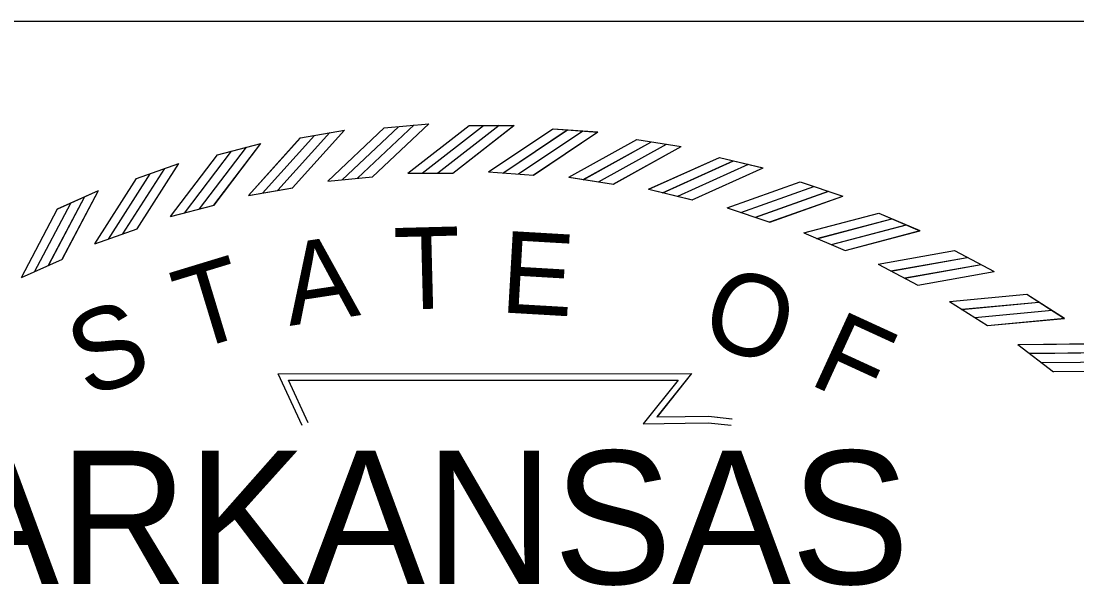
# Model space of a CAD drawing. Extents: x 0 to 1228740, y 0 to 152440.
# Drawn here: x 31.519 to 32.801, y 19.458 to 20.143 of the extents above; entities that cross this region are included whole.
import ezdxf

# ---------------------------------------------------------------- set-up
doc = ezdxf.new("R2010")
doc.units = 0
for name, color, linetype in [('R_Border', 7, 'Continuous'), ('STAMP_Byron', 7, 'Continuous'), ('STAMP_Landon', 7, 'Continuous'), ('STAMP_PP', 7, 'Continuous')]:
    doc.layers.add(name, color=color, linetype=linetype)

msp = doc.modelspace()

# ---------------------------------------------------------------- linework, layer by layer
at = {"layer": 'R_Border'}
msp.add_line((29.1131, 20.1432), (33.4231, 20.1432), dxfattribs=at)
at = {"layer": 'STAMP_Byron'}
for p, q in [((31.8584, 20.0015), (31.912, 20.011)), ((31.8584, 20.0015), (31.912, 20.011)), ((31.9603, 20.0137), (32.0145, 20.0187)), ((31.9603, 20.0137), (32.0145, 20.0187)), ((32.0633, 20.0167), (32.1177, 20.0167)), ((32.0633, 20.0167), (32.1177, 20.0167)), ((32.1652, 20.0126), (32.2195, 20.0087)), ((32.1652, 20.0126), (32.2195, 20.0087)), ((32.2669, 19.9994), (32.3207, 19.991)), ((32.2669, 19.9994), (32.3207, 19.991)), ((31.758, 19.981), (31.8106, 19.9948)), ((31.758, 19.981), (31.8106, 19.9948)), ((31.6595, 19.9522), (31.7108, 19.9704)), ((31.6595, 19.9522), (31.7108, 19.9704)), ((32.3672, 19.9779), (32.4201, 19.965)), ((32.3672, 19.9779), (32.4201, 19.965)), ((31.9891, 19.9588), (32.0436, 19.9588)), ((31.9891, 19.9588), (32.0436, 19.9588)), ((32.0869, 19.9604), (32.1413, 19.9564)), ((32.0869, 19.9604), (32.1413, 19.9564)), ((31.8917, 19.9492), (31.946, 19.9542)), ((31.8917, 19.9492), (31.946, 19.9542)), ((32.1846, 19.9538), (32.2385, 19.9453)), ((32.1846, 19.9538), (32.2385, 19.9453)), ((32.4653, 19.9481), (32.517, 19.9309)), ((32.4653, 19.9481), (32.517, 19.9309)), ((31.5638, 19.9154), (31.6134, 19.9377)), ((31.5638, 19.9154), (31.6134, 19.9377)), ((31.7954, 19.9316), (31.8491, 19.9411)), ((31.7954, 19.9316), (31.8491, 19.9411)), ((32.2814, 19.9392), (32.3344, 19.9263)), ((32.2814, 19.9392), (32.3344, 19.9263)), ((31.7009, 19.9061), (31.7536, 19.92)), ((31.7009, 19.9061), (31.7536, 19.92)), ((32.3766, 19.9166), (32.4283, 19.8994)), ((32.3766, 19.9166), (32.4283, 19.8994)), ((32.5607, 19.9103), (32.6107, 19.889)), ((32.5607, 19.9103), (32.6107, 19.889)), ((31.6088, 19.8729), (31.6602, 19.8911)), ((31.6088, 19.8729), (31.6602, 19.8911)), ((32.4697, 19.8863), (32.5198, 19.8649)), ((32.4697, 19.8863), (32.5198, 19.8649)), ((32.6526, 19.8648), (32.7007, 19.8394)), ((32.6526, 19.8648), (32.7007, 19.8394)), ((31.5198, 19.8322), (31.5696, 19.8545)), ((31.5198, 19.8322), (31.5696, 19.8545)), ((32.5599, 19.8484), (32.6081, 19.8229)), ((32.5599, 19.8484), (32.6081, 19.8229)), ((32.7404, 19.8119), (32.7863, 19.7825)), ((32.7404, 19.8119), (32.7863, 19.7825)), ((32.6467, 19.8032), (32.6926, 19.7738)), ((32.6467, 19.8032), (32.6926, 19.7738)), ((32.7295, 19.7509), (32.7728, 19.7178)), ((32.7295, 19.7509), (32.7728, 19.7178))]:
    msp.add_line(p, q, dxfattribs=at)
for points in [[(31.849, 19.9411), (31.9121, 20.011)], [(31.849, 19.9411), (31.9121, 20.011)], [(31.8916, 19.9492), (31.9602, 20.0136)], [(31.8916, 19.9492), (31.9602, 20.0136)], [(31.9091, 19.9506), (31.9777, 20.0151)], [(31.9091, 19.9506), (31.9777, 20.0151)], [(31.9278, 19.9528), (31.9964, 20.0172)], [(31.9278, 19.9528), (31.9964, 20.0172)], [(31.9459, 19.9543), (32.0145, 20.0187)], [(31.9459, 19.9543), (32.0145, 20.0187)], [(31.989, 19.9588), (32.0632, 20.0167)], [(31.989, 19.9588), (32.0632, 20.0167)], [(32.0065, 19.9586), (32.0807, 20.0165)], [(32.0065, 19.9586), (32.0807, 20.0165)], [(32.0254, 19.959), (32.0996, 20.0169)], [(32.0254, 19.959), (32.0996, 20.0169)], [(32.0435, 19.9589), (32.1178, 20.0168)], [(32.0435, 19.9589), (32.1178, 20.0168)], [(32.0869, 19.9603), (32.1651, 20.0126)], [(32.0869, 19.9603), (32.1651, 20.0126)], [(32.1043, 19.9589), (32.1826, 20.0112)], [(32.1043, 19.9589), (32.1826, 20.0112)], [(32.1232, 19.9579), (32.2015, 20.0102)], [(32.1232, 19.9579), (32.2015, 20.0102)], [(32.1413, 19.9564), (32.2195, 20.0087)], [(32.1413, 19.9564), (32.2195, 20.0087)], [(31.7953, 19.9316), (31.8584, 20.0015)], [(31.7953, 19.9316), (31.8584, 20.0015)], [(31.8126, 19.9344), (31.8757, 20.0043)], [(31.8126, 19.9344), (31.8757, 20.0043)], [(31.8311, 19.9381), (31.8942, 20.008)], [(31.8311, 19.9381), (31.8942, 20.008)], [(32.1845, 19.9538), (32.2668, 19.9994)], [(32.1845, 19.9538), (32.2668, 19.9994)], [(32.2018, 19.9509), (32.2841, 19.9965)], [(32.2018, 19.9509), (32.2841, 19.9965)], [(31.7178, 19.9103), (31.7749, 19.9852)], [(31.7178, 19.9103), (31.7749, 19.9852)], [(31.736, 19.9156), (31.7931, 19.9904)], [(31.736, 19.9156), (31.7931, 19.9904)], [(31.7536, 19.92), (31.8106, 19.9949)], [(31.7536, 19.92), (31.8106, 19.9949)], [(32.2205, 19.9483), (32.3029, 19.994)], [(32.2205, 19.9483), (32.3029, 19.994)], [(32.2384, 19.9454), (32.3207, 19.991)], [(32.2384, 19.9454), (32.3207, 19.991)], [(31.6602, 19.8911), (31.7109, 19.9704)], [(31.6602, 19.8911), (31.7109, 19.9704)], [(31.7008, 19.906), (31.7579, 19.9809)], [(31.7008, 19.906), (31.7579, 19.9809)], [(32.2813, 19.9392), (32.3671, 19.9778)], [(32.2813, 19.9392), (32.3671, 19.9778)], [(32.2983, 19.9349), (32.3841, 19.9736)], [(32.2983, 19.9349), (32.3841, 19.9736)], [(31.6253, 19.8785), (31.676, 19.9578)], [(31.6253, 19.8785), (31.676, 19.9578)], [(31.643, 19.8852), (31.6937, 19.9645)], [(31.643, 19.8852), (31.6937, 19.9645)], [(32.3167, 19.9308), (32.4025, 19.9695)], [(32.3167, 19.9308), (32.4025, 19.9695)], [(32.3343, 19.9263), (32.4201, 19.965)], [(32.3343, 19.9263), (32.4201, 19.965)], [(31.6088, 19.8728), (31.6595, 19.9522)], [(31.6088, 19.8728), (31.6595, 19.9522)], [(32.3765, 19.9166), (32.4653, 19.9481)], [(32.3765, 19.9166), (32.4653, 19.9481)], [(31.5695, 19.8546), (31.6134, 19.9378)], [(31.5695, 19.8546), (31.6134, 19.9378)], [(32.3931, 19.9109), (32.4818, 19.9424)], [(32.3931, 19.9109), (32.4818, 19.9424)], [(32.4112, 19.9054), (32.4999, 19.9368)], [(32.4112, 19.9054), (32.4999, 19.9368)], [(31.5358, 19.8391), (31.5798, 19.9224)], [(31.5358, 19.8391), (31.5798, 19.9224)], [(31.5529, 19.8473), (31.5968, 19.9305)], [(31.5529, 19.8473), (31.5968, 19.9305)], [(32.4283, 19.8995), (32.517, 19.9309)], [(32.4283, 19.8995), (32.517, 19.9309)], [(31.5198, 19.8321), (31.5637, 19.9154)], [(31.5198, 19.8321), (31.5637, 19.9154)], [(32.4696, 19.8863), (32.5606, 19.9103)], [(32.4696, 19.8863), (32.5606, 19.9103)], [(32.4856, 19.8793), (32.5766, 19.9033)], [(32.4856, 19.8793), (32.5766, 19.9033)], [(32.5032, 19.8722), (32.5942, 19.8962)], [(32.5032, 19.8722), (32.5942, 19.8962)], [(32.5198, 19.8649), (32.6108, 19.889)], [(32.5198, 19.8649), (32.6108, 19.889)], [(32.5598, 19.8484), (32.6525, 19.8648)], [(32.5598, 19.8484), (32.6525, 19.8648)], [(32.5752, 19.8401), (32.6679, 19.8565)], [(32.5752, 19.8401), (32.6679, 19.8565)], [(32.5921, 19.8316), (32.6848, 19.848)], [(32.5921, 19.8316), (32.6848, 19.848)], [(32.6081, 19.823), (32.7008, 19.8394)], [(32.6081, 19.823), (32.7008, 19.8394)], [(32.6466, 19.8032), (32.7403, 19.8119)], [(32.6466, 19.8032), (32.7403, 19.8119)], [(32.6613, 19.7936), (32.755, 19.8023)], [(32.6613, 19.7936), (32.755, 19.8023)], [(32.6774, 19.7837), (32.7711, 19.7925)], [(32.6774, 19.7837), (32.7711, 19.7925)], [(32.6926, 19.7738), (32.7863, 19.7826)], [(32.6926, 19.7738), (32.7863, 19.7826)], [(32.7294, 19.7509), (32.8235, 19.7519)], [(32.7294, 19.7509), (32.8235, 19.7519)], [(32.7432, 19.7402), (32.8373, 19.7411)], [(32.7432, 19.7402), (32.8373, 19.7411)], [(32.7585, 19.729), (32.8526, 19.73)], [(32.7585, 19.729), (32.8526, 19.73)], [(31.8606, 19.6526), (31.8316, 19.7154), (32.3334, 19.7157), (32.2915, 19.663), (32.3256, 19.6634), (32.354, 19.6638), (32.3825, 19.6607)], [(31.8606, 19.6526), (31.8316, 19.7154), (32.3334, 19.7157), (32.2915, 19.663), (32.3256, 19.6634), (32.354, 19.6638), (32.3825, 19.6607)], [(32.7728, 19.7179), (32.8669, 19.7188)], [(32.7728, 19.7179), (32.8669, 19.7188)], [(31.8678, 19.6559), (31.844, 19.7074), (32.3169, 19.7077), (32.2748, 19.6548), (32.3257, 19.6555), (32.3537, 19.6559), (32.3816, 19.6528)], [(31.8678, 19.6559), (31.844, 19.7074), (32.3169, 19.7077), (32.2748, 19.6548), (32.3257, 19.6555), (32.3537, 19.6559), (32.3816, 19.6528)]]:
    msp.add_lwpolyline(points, dxfattribs=at)
at = {"layer": 'STAMP_Landon'}
for p, q in [((31.8585, 20.0015), (31.912, 20.011)), ((31.9603, 20.0137), (32.0145, 20.0187)), ((32.0633, 20.0167), (32.1177, 20.0167)), ((32.1652, 20.0126), (32.2195, 20.0087)), ((32.2669, 19.9994), (32.3207, 19.991)), ((31.758, 19.981), (31.8106, 19.9948)), ((31.6595, 19.9522), (31.7108, 19.9704)), ((32.3672, 19.9779), (32.4201, 19.965)), ((31.9891, 19.9588), (32.0436, 19.9588)), ((32.0869, 19.9604), (32.1413, 19.9564)), ((31.8917, 19.9492), (31.946, 19.9542)), ((32.1846, 19.9538), (32.2385, 19.9453)), ((32.4653, 19.9481), (32.517, 19.9309)), ((31.5638, 19.9154), (31.6134, 19.9377)), ((31.7954, 19.9316), (31.8491, 19.9411)), ((32.2814, 19.9392), (32.3344, 19.9263)), ((31.7009, 19.9061), (31.7536, 19.92)), ((32.3766, 19.9166), (32.4283, 19.8994)), ((32.5607, 19.9103), (32.6107, 19.889)), ((31.6088, 19.8729), (31.6602, 19.8911)), ((32.4697, 19.8863), (32.5198, 19.8649)), ((32.6526, 19.8648), (32.7007, 19.8394)), ((31.5198, 19.8322), (31.5696, 19.8545)), ((32.5599, 19.8484), (32.6081, 19.8229)), ((32.7404, 19.8119), (32.7863, 19.7826)), ((32.6467, 19.8032), (32.6926, 19.7738)), ((32.7295, 19.7509), (32.7728, 19.7178))]:
    msp.add_line(p, q, dxfattribs=at)
for points in [[(31.849, 19.9411), (31.9121, 20.011)], [(31.8916, 19.9492), (31.9602, 20.0136)], [(31.9091, 19.9506), (31.9777, 20.0151)], [(31.9278, 19.9528), (31.9964, 20.0172)], [(31.9459, 19.9543), (32.0145, 20.0187)], [(31.989, 19.9588), (32.0632, 20.0167)], [(32.0065, 19.9586), (32.0807, 20.0165)], [(32.0254, 19.959), (32.0996, 20.0169)], [(32.0435, 19.9589), (32.1178, 20.0168)], [(32.0869, 19.9603), (32.1651, 20.0126)], [(32.1043, 19.9589), (32.1826, 20.0112)], [(32.1232, 19.9579), (32.2015, 20.0102)], [(32.1413, 19.9564), (32.2195, 20.0087)], [(31.7953, 19.9316), (31.8584, 20.0015)], [(31.8126, 19.9344), (31.8757, 20.0043)], [(31.8311, 19.9381), (31.8942, 20.008)], [(32.1845, 19.9538), (32.2668, 19.9994)], [(32.2018, 19.9509), (32.2841, 19.9965)], [(31.7178, 19.9103), (31.7749, 19.9852)], [(31.736, 19.9156), (31.7931, 19.9904)], [(31.7536, 19.92), (31.8106, 19.9949)], [(32.2205, 19.9483), (32.3029, 19.994)], [(32.2384, 19.9454), (32.3207, 19.991)], [(31.6602, 19.8911), (31.7109, 19.9704)], [(31.7008, 19.906), (31.7579, 19.9809)], [(32.2813, 19.9392), (32.3671, 19.9778)], [(32.2983, 19.9349), (32.3841, 19.9736)], [(31.6254, 19.8785), (31.676, 19.9578)], [(31.643, 19.8852), (31.6937, 19.9645)], [(32.3167, 19.9308), (32.4025, 19.9695)], [(32.3343, 19.9263), (32.4201, 19.965)], [(31.6088, 19.8728), (31.6595, 19.9522)], [(32.3765, 19.9166), (32.4653, 19.9481)], [(31.5695, 19.8546), (31.6134, 19.9378)], [(32.3931, 19.9109), (32.4818, 19.9424)], [(32.4112, 19.9054), (32.4999, 19.9368)], [(31.5358, 19.8391), (31.5798, 19.9224)], [(31.5529, 19.8473), (31.5969, 19.9305)], [(32.4283, 19.8995), (32.517, 19.9309)], [(31.5198, 19.8321), (31.5637, 19.9154)], [(32.4696, 19.8863), (32.5606, 19.9103)], [(32.4856, 19.8793), (32.5766, 19.9033)], [(32.5032, 19.8722), (32.5942, 19.8962)], [(32.5198, 19.8649), (32.6108, 19.889)], [(32.5598, 19.8484), (32.6525, 19.8648)], [(32.5752, 19.8401), (32.6679, 19.8565)], [(32.5921, 19.8316), (32.6848, 19.848)], [(32.6081, 19.823), (32.7007, 19.8394)], [(32.6466, 19.8032), (32.7403, 19.8119)], [(32.6613, 19.7936), (32.755, 19.8023)], [(32.6774, 19.7837), (32.7711, 19.7925)], [(32.6926, 19.7738), (32.7863, 19.7826)], [(32.7294, 19.7509), (32.8235, 19.7519)], [(32.7432, 19.7402), (32.8373, 19.7411)], [(32.7585, 19.729), (32.8526, 19.73)], [(31.8606, 19.6526), (31.8316, 19.7154), (32.3334, 19.7157), (32.2915, 19.663), (32.3256, 19.6635), (32.354, 19.6638), (32.3825, 19.6607)], [(32.7728, 19.7179), (32.8669, 19.7188)], [(31.8678, 19.6559), (31.844, 19.7074), (32.3169, 19.7077), (32.2748, 19.6548), (32.3257, 19.6555), (32.3537, 19.6559), (32.3816, 19.6528)]]:
    msp.add_lwpolyline(points, dxfattribs=at)
at = {"layer": 'STAMP_PP'}
for p, q in [((31.8584, 20.0015), (31.912, 20.0109)), ((31.9602, 20.0137), (32.0144, 20.0186)), ((32.0633, 20.0167), (32.1177, 20.0167)), ((32.1652, 20.0126), (32.2194, 20.0086)), ((32.2669, 19.9994), (32.3206, 19.9909)), ((31.7579, 19.981), (31.8105, 19.9948)), ((31.6595, 19.9522), (31.7108, 19.9703)), ((32.3671, 19.9778), (32.42, 19.965)), ((31.989, 19.9588), (32.0435, 19.9588)), ((32.0869, 19.9603), (32.1413, 19.9563)), ((31.8916, 19.9492), (31.9459, 19.9542)), ((32.1845, 19.9538), (32.2384, 19.9453)), ((32.4653, 19.9481), (32.5169, 19.9309)), ((31.5637, 19.9154), (31.6134, 19.9377)), ((31.7953, 19.9316), (31.849, 19.941)), ((32.2813, 19.9392), (32.3343, 19.9263)), ((31.7008, 19.9061), (31.7536, 19.9199)), ((32.3766, 19.9166), (32.4283, 19.8994)), ((32.5606, 19.9103), (32.6107, 19.8889)), ((31.6088, 19.8729), (31.6602, 19.891)), ((32.4696, 19.8863), (32.5198, 19.8648)), ((32.6526, 19.8648), (32.7006, 19.8393)), ((31.5198, 19.8321), (31.5695, 19.8545)), ((32.5598, 19.8484), (32.608, 19.8229)), ((32.7404, 19.8119), (32.7862, 19.7825)), ((32.6466, 19.8031), (32.6926, 19.7737)), ((32.7294, 19.7509), (32.7727, 19.7178))]:
    msp.add_line(p, q, dxfattribs=at)
for points in [[(31.849, 19.9411), (31.912, 20.011)], [(31.8916, 19.9491), (31.9602, 20.0136)], [(31.909, 19.9506), (31.9776, 20.015)], [(31.9278, 19.9527), (31.9964, 20.0172)], [(31.9458, 19.9542), (32.0145, 20.0187)], [(31.9889, 19.9587), (32.0632, 20.0166)], [(32.0065, 19.9586), (32.0807, 20.0165)], [(32.0254, 19.959), (32.0996, 20.0169)], [(32.0435, 19.9588), (32.1177, 20.0167)], [(32.0868, 19.9603), (32.1651, 20.0126)], [(32.1043, 19.9588), (32.1825, 20.0111)], [(32.1231, 19.9579), (32.2014, 20.0101)], [(32.1412, 19.9564), (32.2195, 20.0087)], [(31.7953, 19.9315), (31.8583, 20.0014)], [(31.8126, 19.9344), (31.8756, 20.0043)], [(31.8311, 19.9381), (31.8941, 20.008)], [(32.1845, 19.9537), (32.2668, 19.9994)], [(32.2017, 19.9508), (32.2841, 19.9965)], [(31.7178, 19.9103), (31.7748, 19.9852)], [(31.7359, 19.9155), (31.793, 19.9904)], [(31.7535, 19.92), (31.8106, 19.9948)], [(32.2205, 19.9483), (32.3028, 19.994)], [(32.2383, 19.9453), (32.3207, 19.991)], [(31.6601, 19.8911), (31.7108, 19.9704)], [(31.7008, 19.906), (31.7579, 19.9809)], [(32.2812, 19.9391), (32.3671, 19.9778)], [(32.2982, 19.9348), (32.384, 19.9735)], [(31.6253, 19.8785), (31.676, 19.9578)], [(31.643, 19.8852), (31.6937, 19.9645)], [(32.3167, 19.9308), (32.4025, 19.9695)], [(32.3342, 19.9263), (32.4201, 19.965)], [(31.6087, 19.8728), (31.6594, 19.9521)], [(32.3765, 19.9166), (32.4652, 19.9481)], [(31.5694, 19.8545), (31.6134, 19.9378)], [(32.393, 19.9109), (32.4818, 19.9424)], [(32.4111, 19.9053), (32.4998, 19.9368)], [(31.5358, 19.8391), (31.5797, 19.9224)], [(31.5528, 19.8472), (31.5968, 19.9305)], [(32.4282, 19.8994), (32.517, 19.9309)], [(31.5197, 19.8321), (31.5637, 19.9153)], [(32.4695, 19.8863), (32.5606, 19.9103)], [(32.4856, 19.8792), (32.5766, 19.9033)], [(32.5031, 19.8722), (32.5941, 19.8962)], [(32.5197, 19.8649), (32.6107, 19.8889)], [(32.5598, 19.8483), (32.6525, 19.8648)], [(32.5752, 19.84), (32.6679, 19.8565)], [(32.5921, 19.8315), (32.6848, 19.848)], [(32.608, 19.8229), (32.7007, 19.8394)], [(32.6466, 19.8031), (32.7403, 19.8119)], [(32.6612, 19.7935), (32.755, 19.8023)], [(32.6774, 19.7837), (32.7711, 19.7924)], [(32.6925, 19.7738), (32.7863, 19.7825)], [(32.7293, 19.7509), (32.8235, 19.7518)], [(32.7431, 19.7401), (32.8373, 19.7411)], [(32.7584, 19.729), (32.8526, 19.7299)], [(31.8606, 19.6525), (31.8316, 19.7154), (32.3333, 19.7156), (32.2914, 19.663), (32.3255, 19.6634), (32.354, 19.6638), (32.3824, 19.6607)], [(32.7727, 19.7179), (32.8669, 19.7188)], [(31.8678, 19.6559), (31.844, 19.7074), (32.3169, 19.7077), (32.2748, 19.6548), (32.3256, 19.6555), (32.3536, 19.6558), (32.3816, 19.6528)]]:
    msp.add_lwpolyline(points, dxfattribs=at)

# ---------------------------------------------------------------- texts
at = {"layer": 'STAMP_Byron'}
for s, rotation, p in [('T', 1.4789, (31.9731, 19.7931)), ('T', 1.4789, (31.9731, 19.7931)), ('E', 356.672, (32.0998, 19.7901)), ('E', 356.672, (32.0998, 19.7901)), ('A', 8.6788, (31.8453, 19.7734)), ('A', 8.6788, (31.8453, 19.7734)), ('T', 16.9015, (31.7251, 19.742)), ('T', 16.9015, (31.7251, 19.742)), ('O', 341.2218, (32.3401, 19.7561)), ('O', 341.2218, (32.3401, 19.7561)), ('S', 19.7726, (31.5993, 19.6855)), ('S', 19.7726, (31.5993, 19.6855)), ('F', 335.3628, (32.4735, 19.704)), ('F', 335.3628, (32.4735, 19.704))]:
    msp.add_text(s, height=0.099, rotation=rotation, dxfattribs=at).set_placement(p)
msp.add_text('ARKANSAS', height=0.16155, dxfattribs=at).set_placement((31.4214, 19.4603))
msp.add_text('ARKANSAS', height=0.16155, dxfattribs=at).set_placement((31.4214, 19.4603))
at = {"layer": 'STAMP_Landon'}
for s, rotation, p in [('T', 1.4789, (31.9731, 19.7931)), ('E', 356.672, (32.0998, 19.7901)), ('A', 8.6788, (31.8453, 19.7734)), ('T', 16.9015, (31.7251, 19.742)), ('O', 341.2218, (32.3401, 19.7561)), ('S', 19.7726, (31.5993, 19.6855)), ('F', 335.3628, (32.4735, 19.704))]:
    msp.add_text(s, height=0.099, rotation=rotation, dxfattribs=at).set_placement(p)
msp.add_text('ARKANSAS', height=0.16154, dxfattribs=at).set_placement((31.4214, 19.4604))
at = {"layer": 'STAMP_PP'}
for s, rotation, p in [('T', 1.4789, (31.9731, 19.793)), ('E', 356.672, (32.0998, 19.79)), ('A', 8.6788, (31.8453, 19.7733)), ('T', 16.9015, (31.7251, 19.742)), ('O', 341.2218, (32.3401, 19.7561)), ('S', 19.7726, (31.5992, 19.6855)), ('F', 335.3628, (32.4735, 19.7039))]:
    msp.add_text(s, height=0.099, rotation=rotation, dxfattribs=at).set_placement(p)
msp.add_text('ARKANSAS', height=0.16155, dxfattribs=at).set_placement((31.4214, 19.4603))

doc.saveas('drawing.dxf')
